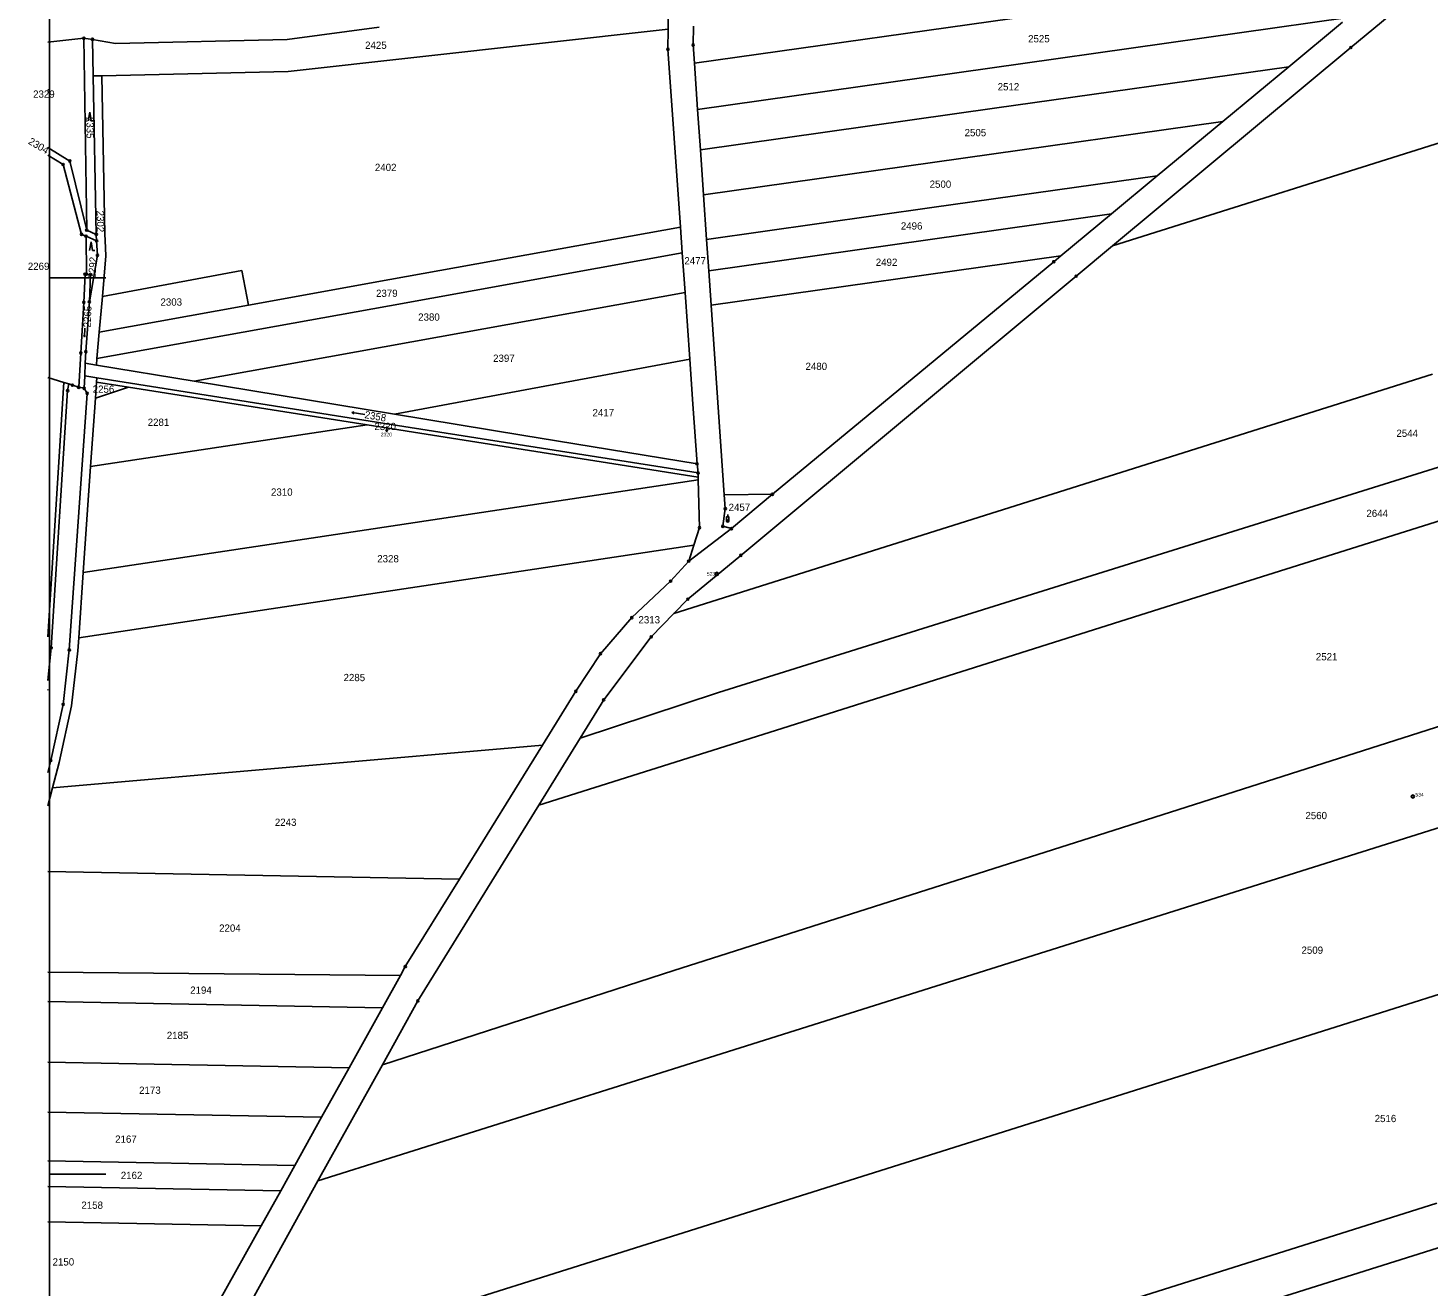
# Model space of a CAD drawing. Extents: x -565355 to -564154, y -1097649 to -1095548.
# Drawn here: x -565353 to -564697, y -1096441 to -1095851 of the extents above; entities that cross this region are included whole.
import ezdxf

# ---------------------------------------------------------------- set-up
doc = ezdxf.new("R2010")
doc.units = 0
for name, color, linetype in [('Vrstva 1', 7, 'Continuous'), ('Vrstva 13', 7, 'Continuous'), ('Vrstva 16', 7, 'Continuous'), ('Vrstva 17', 7, 'Continuous'), ('Vrstva 18', 7, 'Continuous'), ('Vrstva 24', 7, 'Continuous'), ('Vrstva 25', 7, 'Continuous'), ('Vrstva 63', 7, 'Continuous')]:
    doc.layers.add(name, color=color, linetype=linetype)

msp = doc.modelspace()

# ---------------------------------------------------------------- linework, layer by layer
at = {"layer": 'Vrstva 1'}
for p, q in [((-564732.82, -1095859.97), (-564657.54, -1095797.49)), ((-565052.77, -1095836.13), (-565052.84, -1095851.27)), ((-564871.5, -1095843.46), (-565040.48, -1095867.29)), ((-565052.84, -1095851.27), (-565230.93, -1095871.19)), ((-565052.84, -1095851.27), (-565052.89, -1095860.79)), ((-565041.07, -1095858.74), (-565040.85, -1095849.94)), ((-564734.17, -1095845.93), (-564886.58, -1095867.42)), ((-564736.74, -1095848.07), (-564761.9, -1095868.94)), ((-565325.3, -1095945.49), (-565326.62, -1095855.64)), ((-565322.28, -1095873.28), (-565322.62, -1095856.13)), ((-565052.89, -1095860.79), (-565047.04, -1095944.08)), ((-565040.48, -1095867.29), (-565041.07, -1095858.74)), ((-564844.45, -1095952.83), (-564732.82, -1095859.97)), ((-565318.28, -1095873.19), (-565230.93, -1095871.19)), ((-565038.98, -1095888.92), (-565040.48, -1095867.29)), ((-564886.58, -1095867.42), (-565038.98, -1095888.92)), ((-564899.78, -1095888.38), (-564761.9, -1095868.94)), ((-564761.9, -1095868.94), (-564792.8, -1095894.57)), ((-565318.28, -1095873.19), (-565322.28, -1095873.28)), ((-565322.28, -1095873.28), (-565320.79, -1095947.48)), ((-565316.79, -1095947.33), (-565318.28, -1095873.19)), ((-565037.67, -1095907.83), (-565038.98, -1095888.92)), ((-565037.67, -1095907.83), (-564899.78, -1095888.38)), ((-564914.5, -1095911.73), (-564792.8, -1095894.57)), ((-564792.8, -1095894.57), (-564823.53, -1095920.06)), ((-564844.45, -1095952.83), (-564677.35, -1095900.18)), ((-565343.59, -1095906.78), (-565333.17, -1095913.11)), ((-565336.37, -1095914.75), (-565343.59, -1095910.43)), ((-565036.21, -1095928.89), (-565037.67, -1095907.83)), ((-565336.37, -1095914.75), (-565327.73, -1095947.49)), ((-565325.3, -1095945.49), (-565333.17, -1095913.11)), ((-564914.5, -1095911.73), (-565036.21, -1095928.89)), ((-564823.53, -1095920.06), (-564929.14, -1095934.96)), ((-564823.53, -1095920.06), (-564845.07, -1095937.92)), ((-565034.75, -1095949.85), (-565036.21, -1095928.89)), ((-564929.14, -1095934.96), (-565034.75, -1095949.85)), ((-564845.07, -1095937.92), (-565033.74, -1095964.53)), ((-564868.68, -1095957.5), (-564845.07, -1095937.92)), ((-565325.61, -1095948.29), (-565327.73, -1095947.49)), ((-565325.61, -1095948.29), (-565325.42, -1095966.15)), ((-565320.63, -1095950.54), (-565325.61, -1095948.29)), ((-565325.3, -1095945.49), (-565320.79, -1095947.48)), ((-565320.79, -1095947.48), (-565320.63, -1095950.54)), ((-565316.63, -1095950.33), (-565316.79, -1095947.33)), ((-565183.22, -1095968.67), (-565047.04, -1095944.08)), ((-565047.04, -1095944.08), (-565046.19, -1095956.13)), ((-565033.74, -1095964.53), (-565034.75, -1095949.85)), ((-565320.63, -1095950.54), (-565320.28, -1095957.29)), ((-565316.26, -1095957.53), (-565316.63, -1095950.33)), ((-565046.19, -1095956.13), (-565183.34, -1095980.89)), ((-565046.19, -1095956.13), (-565044.88, -1095974.72)), ((-564861.54, -1095967.05), (-564844.45, -1095952.83)), ((-565320.28, -1095957.29), (-565324.05, -1095979.07)), ((-565317.95, -1095976.6), (-565316.26, -1095957.53)), ((-565032.62, -1095980.63), (-564868.68, -1095957.5)), ((-565003.95, -1096069.27), (-564872.06, -1095960.31)), ((-564868.68, -1095957.5), (-564872.06, -1095960.31)), ((-565326.08, -1095966.11), (-565326.66, -1095979.34)), ((-565326.08, -1095966.11), (-565325.42, -1095966.15)), ((-565323.47, -1095966.28), (-565325.42, -1095966.15)), ((-565324.05, -1095979.07), (-565323.47, -1095966.28)), ((-565252.64, -1095964.38), (-565317.95, -1095976.6)), ((-565252.64, -1095964.38), (-565249.5, -1095980.6)), ((-565249.5, -1095980.6), (-565183.22, -1095968.67)), ((-565033.74, -1095964.53), (-565032.62, -1095980.63)), ((-564940.12, -1096032.46), (-564861.54, -1095967.05)), ((-565159.91, -1095995.48), (-565044.88, -1095974.72)), ((-565044.88, -1095974.72), (-565042.69, -1096005.91)), ((-565326.66, -1095979.34), (-565328.04, -1096003.07)), ((-565324.05, -1095979.07), (-565325.74, -1096002.43)), ((-565320.5, -1096005.65), (-565183.34, -1095980.89)), ((-565319.41, -1095993.25), (-565317.95, -1095976.6)), ((-565249.5, -1095980.6), (-565319.41, -1095993.25)), ((-565026.46, -1096069.48), (-565032.62, -1095980.63)), ((-565320.5, -1096005.65), (-565319.41, -1095993.25)), ((-565274.95, -1096016.25), (-565159.91, -1095995.48)), ((-565325.74, -1096002.43), (-565325.98, -1096007.86)), ((-565329.05, -1096019.13), (-565328.04, -1096003.07)), ((-565325.98, -1096007.86), (-565326.25, -1096013.79)), ((-565320.77, -1096008.72), (-565325.98, -1096007.86)), ((-565320.77, -1096008.72), (-565320.5, -1096005.65)), ((-565274.95, -1096016.25), (-565320.77, -1096008.72)), ((-565181, -1096031.67), (-565042.69, -1096005.91)), ((-565042.69, -1096005.91), (-565041.2, -1096027.01)), ((-565336.02, -1096016.85), (-565343.59, -1096014.46)), ((-565326.25, -1096013.79), (-565326.51, -1096019.6)), ((-565320.57, -1096014.69), (-565326.25, -1096013.79)), ((-565320.71, -1096016.69), (-565320.57, -1096014.69)), ((-565320.57, -1096014.69), (-565179.66, -1096036.97)), ((-564694.48, -1096013.05), (-564872.29, -1096069.08)), ((-565343.59, -1096136.1), (-565336.02, -1096016.85)), ((-565334.25, -1096020.7), (-565341.91, -1096141.15)), ((-565333.74, -1096017.57), (-565336.02, -1096016.85)), ((-565333.74, -1096017.57), (-565334.25, -1096020.7)), ((-565332, -1096018.12), (-565333.74, -1096017.57)), ((-565333.45, -1096142.19), (-565325.09, -1096021.97)), ((-565329.05, -1096019.13), (-565332, -1096018.12)), ((-565326.51, -1096019.6), (-565329.05, -1096019.13)), ((-565325.09, -1096021.97), (-565326.51, -1096019.6)), ((-565321.24, -1096024.26), (-565320.71, -1096016.69)), ((-565305.78, -1096019.05), (-565321.24, -1096024.26)), ((-565305.78, -1096019.05), (-565320.71, -1096016.69)), ((-565193.85, -1096036.74), (-565305.78, -1096019.05)), ((-565181, -1096031.67), (-565274.95, -1096016.25)), ((-565323.47, -1096056.29), (-565321.24, -1096024.26)), ((-565041.2, -1096027.01), (-565039.24, -1096054.96)), ((-565121.34, -1096041.48), (-565181, -1096031.67)), ((-565018.71, -1096097.86), (-564940.12, -1096032.46)), ((-565323.47, -1096056.29), (-565193.85, -1096036.74)), ((-565038.71, -1096061.26), (-565193.85, -1096036.74)), ((-565179.66, -1096036.97), (-565038.76, -1096059.25)), ((-565039.24, -1096054.96), (-565121.34, -1096041.48)), ((-565039.24, -1096054.96), (-565038.76, -1096059.25)), ((-565326.92, -1096105.96), (-565323.47, -1096056.29)), ((-565038.76, -1096059.25), (-565038.71, -1096061.26)), ((-565038.71, -1096061.26), (-565038.68, -1096062.49)), ((-564691.7, -1096056.47), (-564788.05, -1096086.67)), ((-565038.68, -1096062.49), (-565182.8, -1096084.22)), ((-565038.68, -1096062.49), (-565038.11, -1096084.88)), ((-564640.06, -1096065.59), (-564822.37, -1096122.99)), ((-564872.29, -1096069.08), (-565050.11, -1096125.11)), ((-565026.46, -1096069.48), (-565003.95, -1096069.27)), ((-565026.01, -1096075.97), (-565026.46, -1096069.48)), ((-565003.95, -1096069.27), (-565023.08, -1096085.33)), ((-565027.2, -1096084.26), (-565026.01, -1096075.97)), ((-565326.92, -1096105.96), (-565182.8, -1096084.22)), ((-565023.08, -1096085.33), (-565043.15, -1096100.6)), ((-565038.11, -1096084.88), (-565040.73, -1096093.06)), ((-565023.08, -1096085.33), (-565027.2, -1096084.26)), ((-564788.05, -1096086.67), (-564884.5, -1096116.9)), ((-565040.73, -1096093.06), (-565184.89, -1096114.8)), ((-565040.73, -1096093.06), (-565043.15, -1096100.6)), ((-565043.15, -1096100.6), (-565051.62, -1096109.98)), ((-565043.56, -1096118.37), (-565018.71, -1096097.86)), ((-565329.05, -1096136.55), (-565326.92, -1096105.96)), ((-565051.62, -1096109.98), (-565069.85, -1096127.02)), ((-565184.89, -1096114.8), (-565329.05, -1096136.55)), ((-565050.11, -1096125.11), (-565043.56, -1096118.37)), ((-565029.14, -1096162.04), (-564884.5, -1096116.9)), ((-565069.85, -1096127.02), (-565084.47, -1096143.94)), ((-565060.7, -1096136), (-565050.11, -1096125.11)), ((-565008.47, -1096181.78), (-564822.37, -1096122.99)), ((-565329.47, -1096142.55), (-565329.05, -1096136.55)), ((-565060.7, -1096136), (-565082.99, -1096165.55)), ((-565341.91, -1096141.15), (-565343.59, -1096156.48)), ((-565333.45, -1096142.19), (-565336.31, -1096167.69)), ((-565332.36, -1096168.34), (-565329.47, -1096142.55)), ((-565084.47, -1096143.94), (-565096.02, -1096161.54)), ((-565096.02, -1096161.54), (-565111.71, -1096186.85)), ((-565029.14, -1096162.04), (-565094.03, -1096183.43)), ((-565082.99, -1096165.55), (-565094.03, -1096183.43)), ((-565336.31, -1096167.69), (-565342.09, -1096193.94)), ((-565338.2, -1096194.88), (-565332.36, -1096168.34)), ((-564854.96, -1096230.14), (-564671.11, -1096171.43)), ((-565113.47, -1096214.92), (-565008.47, -1096181.78)), ((-565094.03, -1096183.43), (-565113.47, -1096214.92)), ((-565111.71, -1096186.85), (-565226.58, -1096196.79)), ((-565111.71, -1096186.85), (-565150.54, -1096249.49)), ((-565343.59, -1096199.61), (-565342.09, -1096193.94)), ((-565341.33, -1096206.7), (-565338.2, -1096194.88)), ((-565226.58, -1096196.79), (-565341.33, -1096206.7)), ((-565343.59, -1096215.25), (-565341.33, -1096206.7)), ((-565170.07, -1096306.6), (-565113.47, -1096214.92)), ((-564849.96, -1096275.34), (-564666.5, -1096217.52)), ((-564854.96, -1096230.14), (-564952.58, -1096261.28)), ((-565251.11, -1096247.68), (-565343.59, -1096246)), ((-565251.11, -1096247.68), (-565150.54, -1096249.49)), ((-565150.54, -1096249.49), (-565175.98, -1096290.52)), ((-564952.58, -1096261.28), (-565050.1, -1096292.39)), ((-564749.01, -1096321.66), (-564584.99, -1096269.98)), ((-565033.43, -1096333.15), (-564849.96, -1096275.34)), ((-565175.98, -1096290.52), (-565178.27, -1096294.64)), ((-565178.27, -1096294.64), (-565343.59, -1096293.2)), ((-565186.68, -1096309.77), (-565178.27, -1096294.64)), ((-565186.65, -1096336.53), (-565050.1, -1096292.39)), ((-565343.59, -1096306.93), (-565186.68, -1096309.77)), ((-565186.68, -1096309.77), (-565202.32, -1096337.9)), ((-565170.07, -1096306.6), (-565186.65, -1096336.53)), ((-564913.03, -1096373.35), (-564749.01, -1096321.66)), ((-565343.59, -1096335.35), (-565202.32, -1096337.9)), ((-565216.9, -1096390.96), (-565033.43, -1096333.15)), ((-565186.65, -1096336.53), (-565216.9, -1096390.96)), ((-565202.32, -1096337.9), (-565215.2, -1096361.06)), ((-565215.2, -1096361.06), (-565343.59, -1096358.74)), ((-565215.2, -1096361.06), (-565227.77, -1096383.67)), ((-565077.05, -1096425.03), (-564913.03, -1096373.35)), ((-565227.77, -1096383.67), (-565343.59, -1096381.57)), ((-565227.77, -1096383.67), (-565234.36, -1096395.52)), ((-565343.59, -1096393.54), (-565234.36, -1096395.52)), ((-565258.49, -1096465.86), (-565216.9, -1096390.96)), ((-565234.36, -1096395.52), (-565243.5, -1096412.03)), ((-564692.48, -1096401.4), (-564856.27, -1096453.02)), ((-565243.5, -1096412.03), (-565343.59, -1096410.03)), ((-565262.99, -1096447.02), (-565243.5, -1096412.03)), ((-564847.26, -1096471.1), (-564683.96, -1096419.71)), ((-565241.07, -1096476.71), (-565077.05, -1096425.03))]:
    msp.add_line(p, q, dxfattribs=at)
at = {"layer": 'Vrstva 13'}
for p, q in [((-565231.27, -1095856.19), (-565188.3, -1095850.34)), ((-565343.59, -1095857.44), (-565326.62, -1095855.64)), ((-565326.62, -1095855.64), (-565322.62, -1095856.13)), ((-565322.62, -1095856.13), (-565311.82, -1095858.04)), ((-565311.82, -1095858.04), (-565231.27, -1095856.19))]:
    msp.add_line(p, q, dxfattribs=at)
at = {"layer": 'Vrstva 16'}
msp.add_line((-565184.66, -1096037.47), (-565184.66, -1096039.84), dxfattribs=at)
msp.add_lwpolyline([(-565184.27, -1096039.05), (-565184.66, -1096039.84), (-565185.06, -1096039.05)], dxfattribs=at)
at = {"layer": 'Vrstva 24'}
msp.add_lwpolyline([(-565343.59, -1096160.72), (-565343.59, -1096161)], dxfattribs=at)
for centre, radius in [((-565326.62, -1095855.64), 0.5), ((-565326.62, -1095855.64), 0.0327), ((-565322.62, -1095856.13), 0.5), ((-565322.62, -1095856.13), 0.0327), ((-565052.89, -1095860.79), 0.5), ((-565052.89, -1095860.79), 0.0327), ((-565041.07, -1095858.74), 0.5), ((-565041.07, -1095858.74), 0.0327), ((-564732.82, -1095859.97), 0.5), ((-564732.82, -1095859.97), 0.0327), ((-565336.37, -1095914.75), 0.5), ((-565336.37, -1095914.75), 0.0327), ((-565333.17, -1095913.11), 0.5), ((-565333.17, -1095913.11), 0.0327), ((-565327.73, -1095947.49), 0.5), ((-565327.73, -1095947.49), 0.0327), ((-565325.61, -1095948.29), 0.5), ((-565325.3, -1095945.49), 0.5), ((-565325.61, -1095948.29), 0.0327), ((-565325.3, -1095945.49), 0.0327), ((-565320.79, -1095947.48), 0.5), ((-565320.79, -1095947.48), 0.0327), ((-565320.63, -1095950.54), 0.5), ((-565320.63, -1095950.54), 0.0327), ((-565320.28, -1095957.29), 0.5), ((-565320.28, -1095957.29), 0.0327), ((-564872.06, -1095960.31), 0.5), ((-564872.06, -1095960.31), 0.0327), ((-565326.08, -1095966.11), 0.5), ((-565326.08, -1095966.11), 0.0327), ((-565325.42, -1095966.15), 0.5), ((-565325.42, -1095966.15), 0.0327), ((-565323.47, -1095966.28), 0.5), ((-565323.47, -1095966.28), 0.0327), ((-564861.54, -1095967.05), 0.5), ((-564861.54, -1095967.05), 0.0327), ((-565326.66, -1095979.34), 0.5), ((-565326.66, -1095979.34), 0.0327), ((-565324.05, -1095979.07), 0.5), ((-565324.05, -1095979.07), 0.0327), ((-565325.74, -1096002.43), 0.5), ((-565325.74, -1096002.43), 0.0327), ((-565328.04, -1096003.07), 0.5), ((-565328.04, -1096003.07), 0.0327), ((-565334.25, -1096020.7), 0.5), ((-565334.25, -1096020.7), 0.0327), ((-565332, -1096018.12), 0.5), ((-565332, -1096018.12), 0.0327), ((-565329.05, -1096019.13), 0.5), ((-565329.05, -1096019.13), 0.0327), ((-565326.51, -1096019.6), 0.5), ((-565326.51, -1096019.6), 0.0327), ((-565325.09, -1096021.97), 0.5), ((-565325.09, -1096021.97), 0.0327), ((-565039.24, -1096054.96), 0.5), ((-565039.24, -1096054.96), 0.0327), ((-565038.76, -1096059.25), 0.5), ((-565038.76, -1096059.25), 0.0327), ((-565003.95, -1096069.27), 0.5), ((-565003.95, -1096069.27), 0.0327), ((-565026.01, -1096075.97), 0.5), ((-565026.01, -1096075.97), 0.0327), ((-565038.11, -1096084.88), 0.5), ((-565038.11, -1096084.88), 0.0327), ((-565027.2, -1096084.26), 0.5), ((-565027.2, -1096084.26), 0.0327), ((-565023.08, -1096085.33), 0.5), ((-565023.08, -1096085.33), 0.0327), ((-565043.15, -1096100.6), 0.5), ((-565043.15, -1096100.6), 0.0327), ((-565018.71, -1096097.86), 0.5), ((-565018.71, -1096097.86), 0.0327), ((-565029.98, -1096106.55), 0.75), ((-565029.98, -1096106.55), 0.0327), ((-565051.62, -1096109.98), 0.5), ((-565051.62, -1096109.98), 0.0327), ((-565043.56, -1096118.37), 0.5), ((-565043.56, -1096118.37), 0.0327), ((-565069.85, -1096127.02), 0.5), ((-565069.85, -1096127.02), 0.0327), ((-565060.7, -1096136), 0.5), ((-565060.7, -1096136), 0.0327), ((-565341.91, -1096141.15), 0.5), ((-565341.91, -1096141.15), 0.0327), ((-565333.45, -1096142.19), 0.5), ((-565333.45, -1096142.19), 0.0327), ((-565084.47, -1096143.94), 0.5), ((-565084.47, -1096143.94), 0.0327), ((-565096.02, -1096161.54), 0.5), ((-565096.02, -1096161.54), 0.0327), ((-565082.99, -1096165.55), 0.5), ((-565082.99, -1096165.55), 0.0327), ((-565336.31, -1096167.69), 0.5), ((-565336.31, -1096167.69), 0.0327), ((-565342.09, -1096193.94), 0.5), ((-565342.09, -1096193.94), 0.0327), ((-564703.75, -1096210.84), 0.75), ((-564703.75, -1096210.84), 0.0327), ((-565175.98, -1096290.52), 0.5), ((-565175.98, -1096290.52), 0.0327), ((-565170.07, -1096306.6), 0.5), ((-565170.07, -1096306.6), 0.0327)]:
    msp.add_circle(centre, radius, dxfattribs=at)
msp.add_arc((-565344.07, -1096160.86), 0.5, 343.7398, 16.2602, dxfattribs=at)
at = {"layer": 'Vrstva 25'}
for p, q in [((-565343.59, -1095879.75), (-565342.89, -1095879.75)), ((-565323.9, -1095890.3), (-565324.64, -1095894.3)), ((-565323.9, -1095890.3), (-565323.17, -1095894.3)), ((-565323.17, -1095894.3), (-565322.17, -1095894.3)), ((-565323.27, -1095951), (-565324.01, -1095955)), ((-565323.27, -1095951), (-565322.54, -1095955)), ((-565322.54, -1095955), (-565321.54, -1095955)), ((-565326.2, -1095991.44), (-565326.4, -1095995.46)), ((-565195.02, -1096031.86), (-565200.94, -1096030.92)), ((-565024.88, -1096079.77), (-565024.88, -1096078.77))]:
    msp.add_line(p, q, dxfattribs=at)
for points in [[(-565326.03, -1095994.8), (-565326.4, -1095995.46), (-565326.7, -1095994.77)], [(-565200.03, -1096031.57), (-565200.94, -1096030.92), (-565199.88, -1096030.58)], [(-565025.38, -1096081.77), (-565025.38, -1096079.77), (-565024.38, -1096079.77), (-565024.38, -1096081.77)]]:
    msp.add_lwpolyline(points, dxfattribs=at)
for radius in [0.5, 0.05]:
    msp.add_circle((-565024.88, -1096081.77), radius, dxfattribs=at)
at = {"layer": 'Vrstva 63'}
for p, q in [((-565342.77, -1095547.8), (-565342.77, -1097647.8)), ((-565316.33, -1095967.8), (-565342.77, -1095967.8)), ((-565316.33, -1096387.8), (-565342.77, -1096387.8))]:
    msp.add_line(p, q, dxfattribs=at)

# ---------------------------------------------------------------- texts
at = {"layer": 'Vrstva 16'}
msp.add_text('2320', height=1.7, dxfattribs=at).set_placement((-565187.45, -1096042.1))
at = {"layer": 'Vrstva 17'}
for s, p in [('523', (-565034.66, -1096107.4)), ('534', (-564702.56, -1096210.83))]:
    msp.add_text(s, height=1.7, dxfattribs=at).set_placement(p)
at = {"layer": 'Vrstva 18'}
for s, p in [('2425', (-565194.81, -1095860.57)), ('2525', (-564884.08, -1095857.52)), ('2512', (-564898.34, -1095880.02)), ('2329', (-565350.42, -1095883.46)), ('2505', (-564913.84, -1095901.51)), ('2402', (-565190.23, -1095917.8)), ('2500', (-564930.23, -1095925.66)), ('2496', (-564943.73, -1095945.23)), ('2269', (-565352.9, -1095964.13)), ('2477', (-565045.18, -1095961.55)), ('2492', (-564955.48, -1095962.23)), ('2379', (-565189.7, -1095976.78)), ('2303', (-565290.72, -1095980.87)), ('2380', (-565169.94, -1095987.93)), ('2397', (-565134.82, -1096007.2)), ('2480', (-564988.4, -1096011)), ('2256', (-565322.49, -1096021.69)), ('2281', (-565296.71, -1096037.18)), ('2417', (-565088.23, -1096032.71)), ('2320', (-565190.47, -1096039.17)), ('2544', (-564711.46, -1096042.36)), ('2310', (-565238.92, -1096069.91)), ('2457', (-565024.44, -1096077.06)), ('2644', (-564725.53, -1096079.9)), ('2328', (-565189.12, -1096101.14)), ('2313', (-565066.71, -1096129.74)), ('2521', (-564749.21, -1096147.04)), ('2285', (-565204.92, -1096156.79)), ('2560', (-564754.11, -1096221.45)), ('2243', (-565237.12, -1096224.59)), ('2204', (-565263.24, -1096274.18)), ('2509', (-564755.95, -1096284.52)), ('2194', (-565276.8, -1096303.25)), ('2185', (-565287.76, -1096324.44)), ('2173', (-565300.73, -1096350.13)), ('2516', (-564721.64, -1096363.38)), ('2167', (-565311.96, -1096373.05)), ('2162', (-565309.32, -1096390.02)), ('2158', (-565327.79, -1096404)), ('2150', (-565341.29, -1096430.56))]:
    msp.add_text(s, height=3.4, dxfattribs=at).set_placement(p)
for s, rotation, p in [('2335', 270.9, (-565325.48, -1095892.49)), ('2304', 329.4, (-565353.01, -1095904.85)), ('2302', 270.9, (-565320.63, -1095936.38)), ('2292', 86.4, (-565321.18, -1095968.24)), ('2265', 87.3, (-565323.49, -1095991.15)), ('2358', 350.1, (-565195.24, -1096033.51))]:
    msp.add_text(s, height=3.4, rotation=rotation, dxfattribs=at).set_placement(p)

doc.saveas('drawing.dxf')
